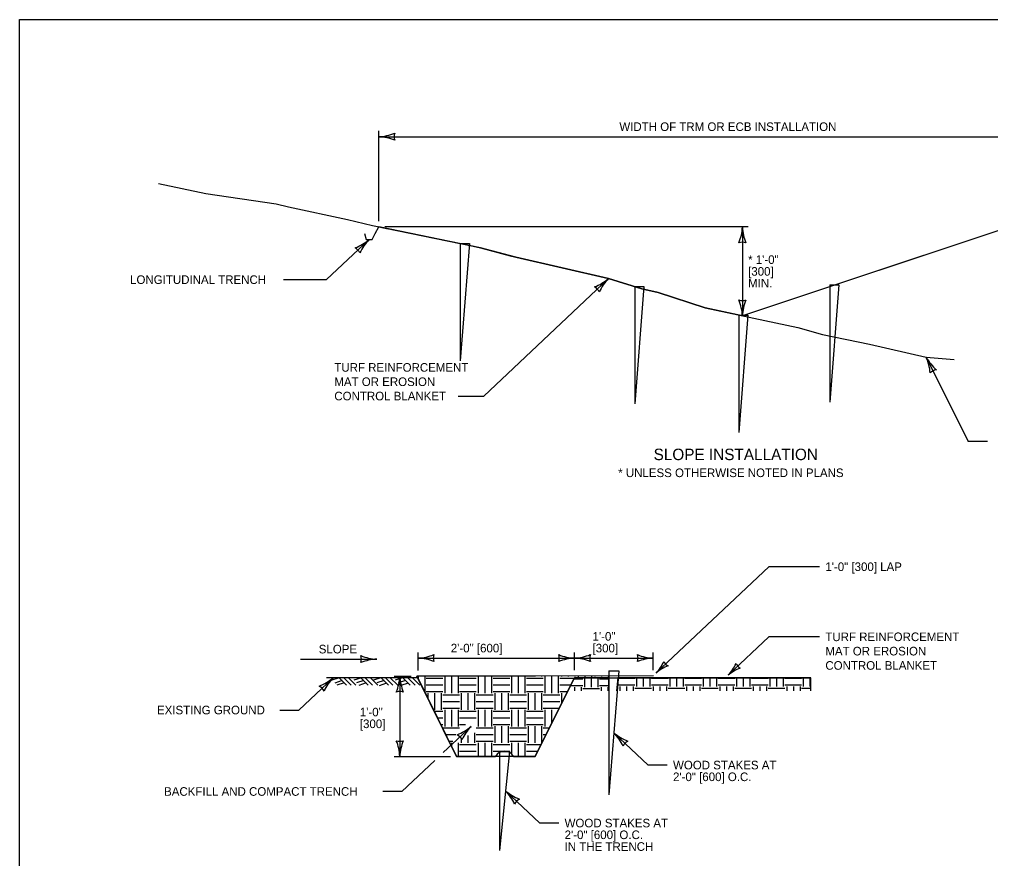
# Model space of a CAD drawing. Extents: x 49977.1 to 50021, y 49987.6 to 50011.4.
# Drawn here: x 49999.38 to 50006.16, y 49993.14 to 49999 of the extents above; entities that cross this region are included whole.
import ezdxf

# ---------------------------------------------------------------- set-up
doc = ezdxf.new("R2010")
doc.units = 0
for name, color, linetype in [('Level 1', 7, 'Continuous'), ('Level 2', 7, 'Continuous'), ('Level 3', 7, 'Continuous'), ('Level 60', 7, 'Continuous')]:
    doc.layers.add(name, color=color, linetype=linetype)

msp = doc.modelspace()

# ---------------------------------------------------------------- linework, layer by layer
at = {"layer": 'Level 1'}
for p, q in [((50008.6533, 49998.3342), (50004.4319, 49996.929)), ((50000.3552, 49997.8542), (50000.686, 49997.7829)), ((50000.686, 49997.7829), (50001.1762, 49997.711)), ((50001.1762, 49997.711), (50001.2627, 49997.689)), ((50001.2627, 49997.689), (50001.6754, 49997.602)), ((50001.6754, 49997.602), (50001.8486, 49997.5587)), ((50001.8486, 49997.5587), (50002.551, 49997.4151)), ((50002.5252, 49997.4334), (50002.4618, 49996.6137)), ((50002.4618, 49997.4334), (50002.4618, 49996.6137)), ((50002.4618, 49997.4334), (50002.5252, 49997.4334)), ((50002.551, 49997.4151), (50002.6023, 49997.4026)), ((50002.6023, 49997.4026), (50002.8092, 49997.3486)), ((50002.8092, 49997.3486), (50002.85, 49997.3379)), ((50002.85, 49997.3379), (50003.4964, 49997.1888)), ((50003.4964, 49997.1888), (50003.7305, 49997.1179)), ((50003.7441, 49997.133), (50003.6806, 49996.3134)), ((50003.6806, 49997.133), (50003.6806, 49996.3134)), ((50003.6806, 49997.133), (50003.7441, 49997.133)), ((50003.7305, 49997.1179), (50003.8436, 49997.0913)), ((50005.1051, 49997.1443), (50005.0416, 49996.3247)), ((50005.0416, 49997.1443), (50005.0416, 49996.3247)), ((50005.0416, 49997.1443), (50005.1051, 49997.1443)), ((50003.8436, 49997.0913), (50004.1717, 49996.9836)), ((50004.1717, 49996.9836), (50004.8199, 49996.8477)), ((50004.4709, 49996.9342), (50004.4075, 49996.1145)), ((50004.4075, 49996.9342), (50004.4075, 49996.1145)), ((50004.4075, 49996.9342), (50004.4709, 49996.9342)), ((50004.8199, 49996.8477), (50004.9905, 49996.7986)), ((50004.9905, 49996.7986), (50005.3184, 49996.7313)), ((50005.3184, 49996.7313), (50005.7155, 49996.6395)), ((50005.7155, 49996.6395), (50005.9114, 49996.6243)), ((50002.1649, 49994.4009), (50001.5274, 49994.4009)), ((50001.6167, 49994.4009), (50001.5652, 49994.3837)), ((50001.6683, 49994.3493), (50001.6167, 49994.4009)), ((50001.6996, 49994.3493), (50001.648, 49994.4009)), ((50001.7319, 49994.3493), (50001.6803, 49994.4009)), ((50001.7712, 49994.4009), (50001.7197, 49994.3837)), ((50001.8198, 49994.3493), (50001.7682, 49994.4009)), ((50001.8501, 49994.3493), (50001.7985, 49994.4009)), ((50001.8865, 49994.3493), (50001.8349, 49994.4009)), ((50001.9076, 49994.4009), (50001.856, 49994.3837)), ((50001.9612, 49994.3493), (50001.9096, 49994.4009)), ((50001.9905, 49994.3493), (50001.9389, 49994.4009)), ((50002.0248, 49994.3493), (50001.9732, 49994.4009)), ((50002.0591, 49994.4009), (50002.0075, 49994.3837)), ((50002.1127, 49994.3493), (50002.0611, 49994.4009)), ((50002.147, 49994.3493), (50002.0955, 49994.4009)), ((50002.1803, 49994.3493), (50002.1288, 49994.4009)), ((50002.1672, 49994.4098), (50002.1672, 49994.3963)), ((50002.2138, 49994.4098), (50002.2138, 49994.3014)), ((50002.2245, 49994.399), (50002.341, 49994.399)), ((50002.2362, 49994.4117), (50002.2362, 49994.4098)), ((50002.2828, 49994.4118), (50002.2828, 49994.4098)), ((50002.3294, 49994.4119), (50002.3294, 49994.4098)), ((50002.3535, 49994.4098), (50002.3535, 49994.2933)), ((50002.4001, 49994.4098), (50002.4001, 49994.2933)), ((50002.4467, 49994.4098), (50002.4467, 49994.2933)), ((50002.4575, 49994.399), (50002.574, 49994.399)), ((50002.4692, 49994.4123), (50002.4692, 49994.4098)), ((50002.5158, 49994.4124), (50002.5158, 49994.4098)), ((50002.5624, 49994.4126), (50002.5624, 49994.4098)), ((50002.5865, 49994.4098), (50002.5865, 49994.2933)), ((50002.6331, 49994.4098), (50002.6331, 49994.2933)), ((50002.6797, 49994.4098), (50002.6797, 49994.2933)), ((50002.6905, 49994.399), (50002.807, 49994.399)), ((50002.7022, 49994.4129), (50002.7022, 49994.4098)), ((50002.7488, 49994.413), (50002.7488, 49994.4098)), ((50002.7954, 49994.4132), (50002.7954, 49994.4098)), ((50002.8195, 49994.4098), (50002.8195, 49994.2933)), ((50002.8661, 49994.4098), (50002.8661, 49994.2933)), ((50002.9127, 49994.4098), (50002.9127, 49994.2933)), ((50002.9235, 49994.399), (50003.04, 49994.399)), ((50002.9352, 49994.4135), (50002.9352, 49994.4098)), ((50002.9818, 49994.4137), (50002.9818, 49994.4098)), ((50003.0284, 49994.4138), (50003.0284, 49994.4098)), ((50003.0525, 49994.4098), (50003.0525, 49994.2933)), ((50003.0991, 49994.4098), (50003.0991, 49994.2933)), ((50003.1457, 49994.4098), (50003.1457, 49994.2933)), ((50003.1565, 49994.399), (50003.2589, 49994.399)), ((50003.1682, 49994.4141), (50003.1682, 49994.4098)), ((50003.2598, 49994.4009), (50003.214, 49994.3092)), ((50003.2148, 49994.4143), (50003.2148, 49994.4098)), ((50003.2598, 49994.4009), (50004.9098, 49994.4009)), ((50003.2598, 49994.4009), (50003.5004, 49994.4009)), ((50003.5004, 49994.4009), (50003.2598, 49994.4009)), ((50003.2614, 49994.4144), (50003.2614, 49994.4098)), ((50003.2855, 49994.4098), (50003.2855, 49994.4009)), ((50003.3291, 49994.4009), (50003.3291, 49994.3356)), ((50003.3321, 49994.4098), (50003.3321, 49994.4009)), ((50003.3757, 49994.4009), (50003.3757, 49994.3356)), ((50003.3787, 49994.4098), (50003.3787, 49994.4009)), ((50003.4012, 49994.4148), (50003.4012, 49994.4098)), ((50003.4223, 49994.4009), (50003.4223, 49994.3356)), ((50003.4478, 49994.4149), (50003.4478, 49994.4098)), ((50003.4944, 49994.415), (50003.4944, 49994.4098)), ((50003.5692, 49994.4492), (50003.5004, 49993.5838)), ((50003.5004, 49994.4492), (50003.5004, 49993.5838)), ((50003.5004, 49994.4492), (50003.5692, 49994.4492)), ((50003.5004, 49994.4009), (50003.5004, 49994.415)), ((50003.5004, 49994.3092), (50003.5004, 49994.4009)), ((50003.5631, 49994.4009), (50003.5517, 49994.3092)), ((50004.9098, 49994.4009), (50003.5631, 49994.4009)), ((50003.5636, 49994.3978), (50003.6801, 49994.3978)), ((50003.6917, 49994.4009), (50003.6917, 49994.3395)), ((50003.7383, 49994.4009), (50003.7383, 49994.3395)), ((50003.7849, 49994.4009), (50003.7849, 49994.3395)), ((50003.7966, 49994.3978), (50003.9131, 49994.3978)), ((50003.9247, 49994.4009), (50003.9247, 49994.3395)), ((50003.9713, 49994.4009), (50003.9713, 49994.3395)), ((50004.0179, 49994.4009), (50004.0179, 49994.3395)), ((50004.0296, 49994.3978), (50004.1461, 49994.3978)), ((50004.1577, 49994.4009), (50004.1577, 49994.3395)), ((50004.2043, 49994.4009), (50004.2043, 49994.3395)), ((50004.2509, 49994.4009), (50004.2509, 49994.3395)), ((50004.2626, 49994.3978), (50004.3791, 49994.3978)), ((50004.3907, 49994.4009), (50004.3907, 49994.3395)), ((50004.4373, 49994.4009), (50004.4373, 49994.3395)), ((50004.4839, 49994.4009), (50004.4839, 49994.3395)), ((50004.4956, 49994.3978), (50004.6121, 49994.3978)), ((50004.6237, 49994.4009), (50004.6237, 49994.3395)), ((50004.6703, 49994.4009), (50004.6703, 49994.3395)), ((50004.7169, 49994.4009), (50004.7169, 49994.3395)), ((50004.7286, 49994.3978), (50004.8451, 49994.3978)), ((50004.8567, 49994.4009), (50004.8567, 49994.3395)), ((50004.9033, 49994.4009), (50004.9033, 49994.3395)), ((50004.9098, 49994.3092), (50004.9098, 49994.4009)), ((50004.9098, 49994.3092), (50004.9098, 49994.4009)), ((50001.6366, 49994.381), (50001.585, 49994.3638)), ((50001.6522, 49994.3653), (50001.6007, 49994.3482)), ((50001.7884, 49994.3814), (50001.7369, 49994.3642)), ((50001.8046, 49994.3642), (50001.753, 49994.3471)), ((50001.9308, 49994.3824), (50001.8792, 49994.3652)), ((50001.946, 49994.3622), (50001.8944, 49994.345)), ((50002.0805, 49994.3815), (50002.0289, 49994.3643)), ((50002.0986, 49994.3633), (50002.0471, 49994.3462)), ((50002.2245, 49994.3524), (50002.341, 49994.3524)), ((50002.4575, 49994.3524), (50002.574, 49994.3524)), ((50002.6905, 49994.3524), (50002.807, 49994.3524)), ((50002.9235, 49994.3524), (50003.04, 49994.3524)), ((50003.1565, 49994.3524), (50003.2356, 49994.3524)), ((50003.233, 49994.3472), (50003.3174, 49994.3472)), ((50003.2563, 49994.3938), (50003.3174, 49994.3938)), ((50003.2601, 49994.3356), (50003.2601, 49994.3092)), ((50003.3067, 49994.3356), (50003.3067, 49994.3092)), ((50003.4339, 49994.3938), (50003.5004, 49994.3938)), ((50003.4339, 49994.3472), (50003.5004, 49994.3472)), ((50003.4465, 49994.3356), (50003.4465, 49994.3092)), ((50003.4931, 49994.3356), (50003.4931, 49994.3092)), ((50003.5636, 49994.3512), (50003.6801, 49994.3512)), ((50003.5761, 49994.3395), (50003.5761, 49994.3092)), ((50003.6227, 49994.3395), (50003.6227, 49994.3092)), ((50003.6693, 49994.3395), (50003.6693, 49994.3092)), ((50003.7966, 49994.3512), (50003.9131, 49994.3512)), ((50003.8091, 49994.3395), (50003.8091, 49994.3092)), ((50003.8557, 49994.3395), (50003.8557, 49994.3092)), ((50003.9023, 49994.3395), (50003.9023, 49994.3092)), ((50004.0296, 49994.3512), (50004.1461, 49994.3512)), ((50004.0421, 49994.3395), (50004.0421, 49994.3092)), ((50004.0887, 49994.3395), (50004.0887, 49994.3092)), ((50004.1353, 49994.3395), (50004.1353, 49994.3092)), ((50004.2626, 49994.3512), (50004.3791, 49994.3512)), ((50004.2751, 49994.3395), (50004.2751, 49994.3092)), ((50004.3217, 49994.3395), (50004.3217, 49994.3092)), ((50004.3683, 49994.3395), (50004.3683, 49994.3092)), ((50004.4956, 49994.3512), (50004.6121, 49994.3512)), ((50004.5081, 49994.3395), (50004.5081, 49994.3092)), ((50004.5547, 49994.3395), (50004.5547, 49994.3092)), ((50004.6013, 49994.3395), (50004.6013, 49994.3092)), ((50004.7286, 49994.3512), (50004.8451, 49994.3512)), ((50004.7411, 49994.3395), (50004.7411, 49994.3092)), ((50004.7877, 49994.3395), (50004.7877, 49994.3092)), ((50004.8343, 49994.3395), (50004.8343, 49994.3092)), ((50002.223, 49994.2825), (50002.2245, 49994.2825)), ((50002.2245, 49994.3058), (50002.341, 49994.3058)), ((50002.2362, 49994.2942), (50002.2362, 49994.2556)), ((50002.2828, 49994.2942), (50002.2828, 49994.1777)), ((50002.3294, 49994.2942), (50002.3294, 49994.1777)), ((50002.341, 49994.2825), (50002.4575, 49994.2825)), ((50002.4575, 49994.3058), (50002.574, 49994.3058)), ((50002.4692, 49994.2942), (50002.4692, 49994.1777)), ((50002.5158, 49994.2942), (50002.5158, 49994.1777)), ((50002.5624, 49994.2942), (50002.5624, 49994.1777)), ((50002.574, 49994.2825), (50002.6905, 49994.2825)), ((50002.6905, 49994.3058), (50002.807, 49994.3058)), ((50002.7022, 49994.2942), (50002.7022, 49994.1777)), ((50002.7488, 49994.2942), (50002.7488, 49994.1777)), ((50002.7954, 49994.2942), (50002.7954, 49994.1777)), ((50002.807, 49994.2825), (50002.9235, 49994.2825)), ((50002.9235, 49994.3058), (50003.04, 49994.3058)), ((50002.9352, 49994.2942), (50002.9352, 49994.1777)), ((50002.9818, 49994.2942), (50002.9818, 49994.1777)), ((50003.0284, 49994.2942), (50003.0284, 49994.1777)), ((50003.04, 49994.2825), (50003.1565, 49994.2825)), ((50003.1565, 49994.3058), (50003.2123, 49994.3058)), ((50003.1682, 49994.2942), (50003.1682, 49994.2176)), ((50003.3174, 49994.3247), (50003.4339, 49994.3247)), ((50003.5541, 49994.3287), (50003.5636, 49994.3287)), ((50003.6801, 49994.3287), (50003.7966, 49994.3287)), ((50003.9131, 49994.3287), (50004.0296, 49994.3287)), ((50004.1461, 49994.3287), (50004.2626, 49994.3287)), ((50004.3791, 49994.3287), (50004.4956, 49994.3287)), ((50004.6121, 49994.3287), (50004.7286, 49994.3287)), ((50004.8451, 49994.3287), (50004.9098, 49994.3287)), ((50002.341, 49994.2359), (50002.4575, 49994.2359)), ((50002.574, 49994.2359), (50002.6905, 49994.2359)), ((50002.807, 49994.2359), (50002.9235, 49994.2359)), ((50003.04, 49994.2359), (50003.1565, 49994.2359)), ((50002.2798, 49994.1668), (50002.341, 49994.1668)), ((50002.341, 49994.1893), (50002.4575, 49994.1893)), ((50002.3535, 49994.1777), (50002.3535, 49994.0612)), ((50002.4001, 49994.1777), (50002.4001, 49994.0612)), ((50002.4467, 49994.1777), (50002.4467, 49994.0612)), ((50002.4575, 49994.1668), (50002.574, 49994.1668)), ((50002.574, 49994.1893), (50002.6905, 49994.1893)), ((50002.5865, 49994.1777), (50002.5865, 49994.0612)), ((50002.6331, 49994.1777), (50002.6331, 49994.0612)), ((50002.6797, 49994.1777), (50002.6797, 49994.0612)), ((50002.6905, 49994.1668), (50002.807, 49994.1668)), ((50002.807, 49994.1893), (50002.9235, 49994.1893)), ((50002.8195, 49994.1777), (50002.8195, 49994.0612)), ((50002.8661, 49994.1777), (50002.8661, 49994.0612)), ((50002.9127, 49994.1777), (50002.9127, 49994.0612)), ((50002.9235, 49994.1668), (50003.04, 49994.1668)), ((50003.04, 49994.1893), (50003.154, 49994.1893)), ((50003.0525, 49994.1777), (50003.0525, 49994.0612)), ((50003.0991, 49994.1777), (50003.0991, 49994.0795)), ((50003.1457, 49994.1777), (50003.1457, 49994.1727)), ((50002.3026, 49994.1202), (50002.341, 49994.1202)), ((50002.3255, 49994.0736), (50002.341, 49994.0736)), ((50002.4575, 49994.1202), (50002.574, 49994.1202)), ((50002.4575, 49994.0736), (50002.4991, 49994.0736)), ((50002.6905, 49994.1202), (50002.807, 49994.1202)), ((50002.6905, 49994.0736), (50002.807, 49994.0736)), ((50002.7022, 49994.062), (50002.7022, 49993.9455)), ((50002.7488, 49994.062), (50002.7488, 49993.9455)), ((50002.7954, 49994.062), (50002.7954, 49993.9455)), ((50002.9235, 49994.1202), (50003.04, 49994.1202)), ((50002.9235, 49994.0736), (50003.04, 49994.0736)), ((50002.9352, 49994.062), (50002.9352, 49993.9455)), ((50002.9818, 49994.062), (50002.9818, 49993.9455)), ((50003.0284, 49994.062), (50003.0284, 49993.9455)), ((50002.341, 49994.0503), (50002.4575, 49994.0503)), ((50002.3598, 49994.0037), (50002.4309, 49994.0037)), ((50002.5158, 49993.9981), (50002.5158, 49993.9455)), ((50002.5624, 49994.0149), (50002.5624, 49993.9455)), ((50002.574, 49994.0503), (50002.6905, 49994.0503)), ((50002.574, 49994.0037), (50002.6905, 49994.0037)), ((50002.807, 49994.0503), (50002.9235, 49994.0503)), ((50002.807, 49994.0037), (50002.9235, 49994.0037)), ((50003.04, 49994.0503), (50003.0845, 49994.0503)), ((50003.04, 49994.0037), (50003.0612, 49994.0037)), ((50002.3827, 49993.9571), (50002.409, 49993.9571)), ((50002.4001, 49993.9455), (50002.4001, 49993.9215)), ((50002.4467, 49993.9455), (50002.4467, 49993.8509)), ((50002.4575, 49993.9346), (50002.574, 49993.9346)), ((50002.4692, 49993.9801), (50002.4692, 49993.9455)), ((50002.574, 49993.9571), (50002.6905, 49993.9571)), ((50002.5865, 49993.9455), (50002.5865, 49993.8509)), ((50002.6331, 49993.9455), (50002.6331, 49993.8509)), ((50002.6797, 49993.9455), (50002.6797, 49993.8509)), ((50002.6905, 49993.9346), (50002.807, 49993.9346)), ((50002.807, 49993.9571), (50002.9235, 49993.9571)), ((50002.8195, 49993.9455), (50002.8195, 49993.8685)), ((50002.8661, 49993.9455), (50002.8661, 49993.8509)), ((50002.9127, 49993.9455), (50002.9127, 49993.8509)), ((50002.9235, 49993.9346), (50003.0267, 49993.9346)), ((50002.4575, 49993.888), (50002.574, 49993.888)), ((50002.6905, 49993.888), (50002.761, 49993.888)), ((50002.7362, 49993.8861), (50002.7362, 49993.1932)), ((50002.8049, 49993.8861), (50002.7362, 49993.1932)), ((50002.7362, 49993.8861), (50002.8049, 49993.8861)), ((50002.7802, 49993.888), (50002.807, 49993.888)), ((50002.9235, 49993.888), (50003.0034, 49993.888))]:
    msp.add_line(p, q, dxfattribs=at)
msp.add_lwpolyline([(49999.3835, 49998.9992), (50016.7501, 49998.9992), (50016.7501, 49987.7988), (49999.3835, 49987.7988)], close=True, dxfattribs=at)
for points in [[(50006.97, 49997.775), (50004.4319, 49996.929), (50004.1717, 49996.9836), (50003.8436, 49997.0913), (50003.7305, 49997.1179), (50003.4964, 49997.1888), (50002.85, 49997.3379), (50002.6023, 49997.4026), (50001.8939, 49997.5493)], [(50001.7932, 49997.5033), (50001.8043, 49997.4615), (50001.8458, 49997.4618), (50001.867, 49997.5043), (50001.8939, 49997.5493), (50001.9582, 49997.536)], [(50003.5004, 49994.415), (50002.1597, 49994.4115), (50002.1649, 49994.4009), (50002.4348, 49993.8509), (50002.7087, 49993.8509)], [(50002.8325, 49993.8509), (50002.9848, 49993.8509), (50003.214, 49994.3092), (50003.2598, 49994.4009)]]:
    msp.add_lwpolyline(points, dxfattribs=at)
msp.add_arc((50002.7706, 49993.8192), 0.0695, 27.10314, 152.89686, dxfattribs=at)
at = {"layer": 'Level 3'}
for p, q in [((50001.8939, 49997.5894), (50001.8939, 49998.2199)), ((50001.8939, 49998.1799), (50006.967, 49998.1799)), ((50004.4719, 49997.5493), (50001.9345, 49997.5493)), ((50004.4319, 49997.5493), (50004.4319, 49996.929)), ((50001.8251, 49997.4616), (50001.5277, 49997.1814)), ((50001.2271, 49997.1814), (50001.5277, 49997.1814)), ((50003.4964, 49997.1888), (50002.6257, 49996.3684)), ((50005.7155, 49996.6395), (50006.0093, 49996.0509)), ((50002.4477, 49996.3684), (50002.6257, 49996.3684)), ((50006.1427, 49996.0509), (50006.0093, 49996.0509)), ((50003.8304, 49994.4352), (50004.6169, 49995.1763)), ((50004.9713, 49995.1763), (50004.6169, 49995.1763)), ((50004.3341, 49994.4202), (50004.6169, 49994.6867)), ((50004.9713, 49994.6867), (50004.6169, 49994.6867)), ((50002.1672, 49994.4515), (50002.1672, 49994.578)), ((50002.1672, 49994.538), (50003.2598, 49994.538)), ((50003.2598, 49994.4544), (50003.2598, 49994.578)), ((50003.2598, 49994.538), (50003.8098, 49994.538)), ((50003.8098, 49994.4544), (50003.8098, 49994.578)), ((50001.3468, 49994.5308), (50001.8783, 49994.5308)), ((50001.5741, 49994.4009), (50001.3347, 49994.1753)), ((50001.9997, 49994.4115), (50002.1197, 49994.4115)), ((50002.0397, 49994.4115), (50002.0397, 49993.8509)), ((50001.2013, 49994.1753), (50001.3347, 49994.1753)), ((50002.5369, 49994.0608), (50002.3433, 49993.8783)), ((50003.5348, 49994.0165), (50003.7742, 49993.7909)), ((50001.9997, 49993.8509), (50002.3948, 49993.8509)), ((50002.2851, 49993.8235), (50002.0547, 49993.6064)), ((50003.9076, 49993.7909), (50003.7742, 49993.7909)), ((50002.0547, 49993.6064), (50001.9213, 49993.6064)), ((50002.7777, 49993.6113), (50003.0171, 49993.3858)), ((50003.1505, 49993.3858), (50003.0171, 49993.3858))]:
    msp.add_line(p, q, dxfattribs=at)
for centre, radius, start, end in [((50001.8772, 49998.5174), 0.3379, 272.82731, 292.07716), ((50002.0799, 49998.1799), 0.0794, 162.13882, 197.86118), ((50001.8806, 49997.8577), 0.3224, 67.45601, 87.63952), ((50004.1098, 49997.5626), 0.3224, 337.45601, 357.63952), ((50004.7694, 49997.566), 0.3379, 182.82731, 202.07716), ((50001.6058, 49997.7187), 0.3379, 291.21884, 310.46869), ((50002.0557, 49997.2363), 0.3224, 135.65648, 155.83999), ((50001.6897, 49997.3341), 0.0794, 25.43482, 61.15718), ((50004.4319, 49997.3633), 0.0794, 72.13882, 107.86118), ((50003.2771, 49997.4459), 0.3379, 291.21884, 310.46869), ((50003.727, 49996.9634), 0.3224, 135.65648, 155.83999), ((50003.3611, 49997.0613), 0.0794, 25.43482, 61.15718), ((50004.4319, 49997.115), 0.0794, 252.13882, 287.86118), ((50004.0944, 49996.9124), 0.3379, 2.82731, 22.07716), ((50004.7541, 49996.9157), 0.3224, 157.45601, 177.63952), ((50005.4213, 49996.5075), 0.3224, 3.98414, 24.16765), ((50006.01, 49996.8051), 0.3379, 209.35544, 228.60529), ((50005.7985, 49996.4731), 0.0794, 98.66695, 134.38931), ((50001.8916, 49994.8529), 0.3224, 247.45601, 267.63952), ((50001.6924, 49994.5308), 0.0794, 342.13882, 17.86118), ((50002.1505, 49994.8755), 0.3379, 272.82731, 292.07716), ((50002.1539, 49994.2158), 0.3224, 67.45601, 87.63952), ((50002.3531, 49994.538), 0.0794, 162.13882, 197.86118), ((50003.2731, 49994.8602), 0.3224, 247.45601, 267.63952), ((50003.0739, 49994.538), 0.0794, 342.13882, 17.86118), ((50003.2765, 49994.2005), 0.3379, 92.82731, 112.07716), ((50003.2431, 49994.8755), 0.3379, 272.82731, 292.07716), ((50003.2465, 49994.2158), 0.3224, 67.45601, 87.63952), ((50003.4458, 49994.538), 0.0794, 162.13882, 197.86118), ((50003.8231, 49994.8602), 0.3224, 247.45601, 267.63952), ((50003.6239, 49994.538), 0.0794, 342.13882, 17.86118), ((50003.8265, 49994.2005), 0.3379, 92.82731, 112.07716), ((50001.895, 49994.1933), 0.3379, 92.82731, 112.07716), ((50003.6292, 49994.6285), 0.279, 315.65648, 335.83999), ((50004.0185, 49994.211), 0.2924, 111.21884, 130.46869), ((50003.9458, 49994.5438), 0.0687, 205.43482, 241.15718), ((50004.1329, 49994.6135), 0.279, 315.65648, 335.83999), ((50004.5222, 49994.1961), 0.2924, 111.21884, 130.46869), ((50004.4496, 49994.5289), 0.0687, 205.43482, 241.15718), ((50001.3548, 49994.658), 0.3379, 291.21884, 310.46869), ((50001.8047, 49994.1755), 0.3224, 135.65648, 155.83999), ((50001.7175, 49994.4248), 0.3224, 337.45601, 357.63952), ((50002.3772, 49994.4282), 0.3379, 182.82731, 202.07716), ((50001.4388, 49994.2734), 0.0794, 25.43482, 61.15718), ((50002.0397, 49994.2256), 0.0794, 72.13882, 107.86118), ((50002.3176, 49994.3178), 0.3379, 291.21884, 310.46869), ((50002.7675, 49993.8354), 0.3224, 135.65648, 155.83999), ((50002.4016, 49993.9332), 0.0794, 25.43482, 61.15718), ((50003.3042, 49993.7911), 0.3224, 24.16001, 44.34352), ((50003.7541, 49994.2736), 0.3379, 229.53131, 248.78116), ((50002.0397, 49994.0368), 0.0794, 252.13882, 287.86118), ((50001.7022, 49993.8342), 0.3379, 2.82731, 22.07716), ((50002.3619, 49993.8376), 0.3224, 157.45601, 177.63952), ((50003.6701, 49993.889), 0.0794, 118.84282, 154.56518), ((50002.5471, 49993.386), 0.3224, 24.16001, 44.34352), ((50002.997, 49993.8684), 0.3379, 229.53131, 248.78116), ((50002.913, 49993.4838), 0.0794, 118.84282, 154.56518)]:
    msp.add_arc(centre, radius, start, end, dxfattribs=at)
at = {"layer": 'Level 60'}
msp.add_lwpolyline([(50003.2598, 49994.4009), (50002.9848, 49993.8509), (50002.4348, 49993.8509), (50002.1597, 49994.4115), (50003.8103, 49994.4158)], dxfattribs=at)

# ---------------------------------------------------------------- texts
at = {"layer": 'Level 2'}
for s, height, p in [('WIDTH OF TRM OR ECB INSTALLATION', 0.06, (50003.5729, 49998.2199)), ('* 1\'-0" ', 0.06, (50004.4719, 49997.2912)), ('[300] ', 0.06, (50004.4719, 49997.2092)), ('LONGITUDINAL TRENCH', 0.06, (50000.1564, 49997.1514)), ('MIN.', 0.06, (50004.4719, 49997.1272)), ('TURF REINFORCEMENT ', 0.06, (50001.5825, 49996.5384)), ('MAT OR EROSION ', 0.06, (50001.5825, 49996.4384)), ('CONTROL BLANKET', 0.06, (50001.5825, 49996.3384)), ('SLOPE INSTALLATION', 0.08, (50003.8119, 49995.9209)), ('* UNLESS OTHERWISE NOTED IN PLANS', 0.06, (50003.5647, 49995.8024)), ('1\'-0" [300] LAP', 0.06, (50005.0113, 49995.1463)), ('1\'-0" ', 0.06, (50003.3856, 49994.66)), ('TURF REINFORCEMENT ', 0.06, (50005.0113, 49994.6567)), ('SLOPE', 0.06, (50001.4738, 49994.5708)), ('2\'-0" [600]', 0.06, (50002.3959, 49994.578)), ('[300]', 0.06, (50003.3856, 49994.578)), ('MAT OR EROSION', 0.06, (50005.0113, 49994.5567)), ('CONTROL BLANKET', 0.06, (50005.0113, 49994.4567)), ('EXISTING GROUND', 0.06, (50000.344, 49994.1453)), ('1\'-0" ', 0.06, (50001.7606, 49994.1312)), ('[300]', 0.06, (50001.7606, 49994.0492)), ('WOOD STAKES AT', 0.06, (50003.9476, 49993.7609)), ('2\'-0" [600] O.C.', 0.06, (50003.9476, 49993.6789)), ('BACKFILL AND COMPACT TRENCH', 0.06, (50000.3938, 49993.5764)), ('WOOD STAKES AT', 0.06, (50003.1905, 49993.3558)), ('2\'-0" [600] O.C.', 0.06, (50003.1905, 49993.2738)), ('IN THE TRENCH', 0.06, (50003.1905, 49993.1918))]:
    msp.add_text(s, height=height, dxfattribs=at).set_placement(p)

doc.saveas('drawing.dxf')
